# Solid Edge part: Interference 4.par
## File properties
Last saved by: Lee
Revision: 59
Accuracy: 0.990
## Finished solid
Body 1: solid body, 4 faces, 4 edges, 0 vertices.
  Faces by surface: cylinder 4
  Edges by curve: intersection 4
Bounding box of the edges (mm): 99.073 x 219.082 x 338.116, from (812.0535, -376.5377, 292.9713) to (911.127, -157.4555, 631.0878).
Cylindrical faces by radius (mm): R91 x1, R109.5375 x1, R850 x1, R875.4 x1
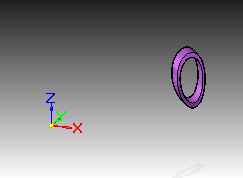
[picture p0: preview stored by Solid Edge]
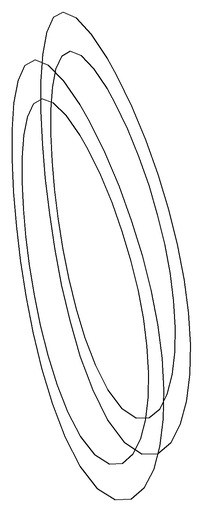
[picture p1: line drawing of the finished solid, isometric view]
